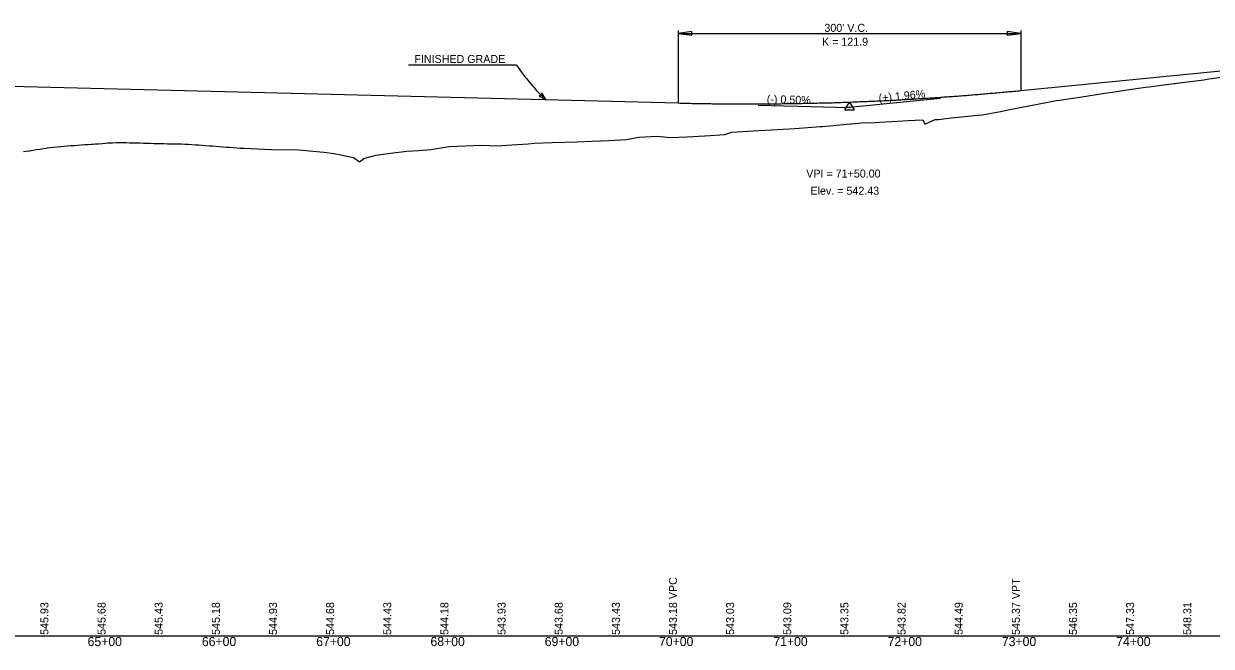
# Model space of a CAD drawing. Extents: x 49922 to 54713, y 49991 to 62800.
# Drawn here: x 52427 to 53466, y 61991 to 62535 of the extents above; entities that cross this region are included whole.
import ezdxf

# ---------------------------------------------------------------- set-up
doc = ezdxf.new("R2010")
doc.units = 0
for name, color, linetype in [('RD_DDB_GradeTX', 7, 'Continuous'), ('RD_DDB_Profile_EX', 7, 'Continuous'), ('RD_DDB_Profile_Lbl', 7, 'Continuous'), ('RD_DDB_Profile_PR', 7, 'Continuous'), ('RD_DDB_StaTX', 7, 'Continuous'), ('RD_DDB_StripGrade', 7, 'Continuous'), ('RD_DDB_VCLbl', 7, 'Continuous'), ('RD_GPK_Profile_Cell', 7, 'Continuous'), ('RD_TX_Profile', 7, 'Continuous')]:
    doc.layers.add(name, color=color, linetype=linetype)

msp = doc.modelspace()

# ---------------------------------------------------------------- linework, layer by layer
at = {"layer": 'RD_DDB_GradeTX'}
for p, q in [((53229.6, 62469.9), (53150, 62462.1)), ((53070, 62464.1), (53150, 62462.1)), ((53146, 62459.8), (53150, 62466.7)), ((53146, 62459.8), (53154, 62459.8)), ((53150, 62466.7), (53154, 62459.8))]:
    msp.add_line(p, q, dxfattribs=at)
msp.add_circle((53150, 62462.1), 0.529, dxfattribs=at)
at = {"layer": 'RD_DDB_Profile_EX'}
for points in [[(52783.7, 62425.3), (52799.8, 62427.8), (52827.9, 62429), (52841.5, 62428.3), (52854.6, 62429.3), (52868.8, 62430.3), (52874.3, 62430.7), (52889.8, 62431.5), (52911.6, 62431.9), (52924.9, 62432.5), (52939.4, 62433.2), (52954.9, 62434), (52965.6, 62436.1), (52981.7, 62437), (52993.4, 62435.7), (53007.7, 62436.4), (53023.2, 62437.2), (53023.6, 62437.2), (53041, 62438.5), (53046.9, 62440.3), (53070.3, 62441.9), (53081.8, 62442.3), (53102.2, 62443.7), (53124.5, 62445.3), (53126.2, 62445.4), (53150.7, 62447.6), (53151.9, 62447.7), (53160.5, 62448.5), (53172.5, 62448.9), (53176.2, 62449.2), (53192.2, 62449.9), (53201.3, 62450.5), (53207.4, 62450.9), (53214.1, 62451.3), (53215.8, 62447.4), (53216.4, 62447.8), (53225, 62451.4), (53227.7, 62451.6), (53238.9, 62453), (53256.3, 62454.7), (53259, 62455), (53265.9, 62455.6), (53282.2, 62458.6), (53290.3, 62460.2), (53306.8, 62463.3), (53331.2, 62468), (53333.6, 62468.4), (53353.2, 62471.4), (53358.8, 62472.2), (53373.3, 62474.5), (53383.9, 62476), (53393, 62477.4), (53409, 62479.6), (53412.3, 62480.1), (53422.7, 62481.6), (53434.1, 62482.9), (53434.9, 62483), (53436.5, 62483.2), (53459.9, 62486.3), (53464.5, 62486.9), (53484.9, 62489.6)], [(52427.3, 62423.4), (52429.4, 62423.8), (52432.4, 62424.2), (52435.4, 62424.7), (52438.5, 62425.2), (52441.5, 62425.6), (52444.5, 62426.1), (52447.5, 62426.5), (52448, 62426.6), (52450.6, 62426.9), (52453.6, 62427.3), (52456.6, 62427.6), (52459.6, 62428), (52460, 62428), (52462.7, 62428.2), (52465.7, 62428.4), (52468.7, 62428.6), (52471.7, 62428.8), (52474.7, 62429), (52477.8, 62429.3), (52480.8, 62429.5), (52483.8, 62429.6), (52486.8, 62429.8), (52488.3, 62429.9), (52489.9, 62430.1), (52492.9, 62430.3), (52495.9, 62430.6), (52498.9, 62430.8), (52500.7, 62431), (52502, 62431.1), (52505, 62431.2), (52508, 62431.4), (52509.8, 62431.5), (52511, 62431.4), (52514, 62431.3), (52517.1, 62431.3), (52520.1, 62431.2), (52523.1, 62431.1), (52526.1, 62431), (52529.2, 62431), (52532.2, 62430.9), (52535.2, 62430.8), (52538.2, 62430.7), (52541.2, 62430.6), (52544.3, 62430.5), (52547.3, 62430.4), (52550.3, 62430.4), (52553.3, 62430.3), (52556.4, 62430.2), (52559.4, 62430.2), (52560.6, 62430.3), (52561.3, 62430.3), (52562.4, 62430.2), (52565.6, 62430.1), (52568.5, 62430), (52570, 62429.9), (52571.5, 62429.8), (52574.5, 62429.6), (52577.5, 62429.4), (52580.5, 62429.2), (52583.6, 62429), (52586.6, 62428.7), (52589.6, 62428.5), (52592.6, 62428.3), (52595.7, 62428.1), (52598.7, 62427.9), (52601.7, 62427.6), (52604.7, 62427.4), (52607.8, 62427.2), (52610.8, 62427), (52613.8, 62426.8), (52616.8, 62426.5), (52620.2, 62426.3), (52631.9, 62425.7), (52644.2, 62425.1), (52668.1, 62425), (52690, 62422.8), (52699, 62421.6), (52716.1, 62418.2), (52720.9, 62414.8), (52721.3, 62414.4), (52724.9, 62417.3), (52735.4, 62420.4), (52748.2, 62421.9), (52762.7, 62423.8), (52772.7, 62424.5), (52783.7, 62425.3)]]:
    msp.add_lwpolyline(points, dxfattribs=at)
at = {"layer": 'RD_DDB_Profile_PR'}
for p, q in [((51800, 62495.9), (53000, 62465.9)), ((53300, 62476.8), (53500, 62496.4))]:
    msp.add_line(p, q, dxfattribs=at)
msp.add_spline([(53000, 62465.9), (53006, 62465.7), (53012, 62465.6), (53018, 62465.5), (53024, 62465.4), (53030, 62465.3), (53036, 62465.2), (53042, 62465.2), (53048, 62465.1), (53054, 62465.1), (53060, 62465.1), (53066, 62465.1), (53072, 62465.1), (53078, 62465.2), (53084, 62465.2), (53090, 62465.3), (53096, 62465.4), (53102, 62465.5), (53108, 62465.6), (53114, 62465.7), (53120, 62465.8), (53126, 62466), (53132, 62466.1), (53138, 62466.3), (53144, 62466.5), (53150, 62466.7), (53156, 62467), (53162, 62467.2), (53168, 62467.5), (53174, 62467.7), (53180, 62468), (53186, 62468.3), (53192, 62468.6), (53198, 62469), (53204, 62469.3), (53210, 62469.7), (53216, 62470), (53222, 62470.4), (53228, 62470.8), (53234, 62471.3), (53240, 62471.7), (53246, 62472.1), (53252, 62472.6), (53258, 62473.1), (53264, 62473.6), (53270, 62474.1), (53276, 62474.6), (53282, 62475.1), (53288, 62475.7), (53294, 62476.2), (53300, 62476.8)], degree=3, dxfattribs=at)
at = {"layer": 'RD_DDB_VCLbl'}
for p, q in [((53000, 62529.3), (53000, 62465.9)), ((53012, 62528.3), (53000, 62526.8)), ((53000, 62526.8), (53300, 62526.8)), ((53000, 62526.8), (53012, 62525.3)), ((53012, 62525.3), (53012, 62528.3)), ((53300, 62526.8), (53288, 62528.3)), ((53288, 62528.3), (53288, 62525.3)), ((53288, 62525.3), (53300, 62526.8)), ((53300, 62529.3), (53300, 62476.8))]:
    msp.add_line(p, q, dxfattribs=at)
at = {"layer": 'RD_GPK_Profile_Cell'}
msp.add_line((50000, 62000), (54700, 62000), dxfattribs=at)
at = {"layer": 'RD_TX_Profile'}
msp.add_line((52858.7, 62498.9), (52764.2, 62498.9), dxfattribs=at)
msp.add_lwpolyline([(52878.3, 62472), (52884.5, 62468.7), (52880.7, 62474.6)], close=True, dxfattribs=at)
msp.add_arc((53002, 62594.8), 172.4, 213.7803, 226.9981, dxfattribs=at)

# ---------------------------------------------------------------- texts
at = {"layer": 'RD_DDB_GradeTX'}
for s, rotation, p in [('(-) 0.50%', 358.5679, (53077.5, 62465.9)), ('(+) 1.96%', 5.5985, (53175.8, 62466.7))]:
    msp.add_text(s, height=7, rotation=rotation, dxfattribs=at).set_placement(p)
at = {"layer": 'RD_DDB_Profile_Lbl'}
for s, p in [('VPI = 71+50.00', (53112.1, 62400.7)), ('Elev. = 542.43', (53115.8, 62385.7))]:
    msp.add_text(s, height=7, dxfattribs=at).set_placement(p)
at = {"layer": 'RD_DDB_StaTX'}
for s, p in [('65+00', (52483.3, 61991)), ('66+00', (52583.3, 61991)), ('67+00', (52683.3, 61991)), ('68+00', (52783.3, 61991)), ('69+00', (52883.3, 61991)), ('70+00', (52983.3, 61991)), ('71+00', (53083.3, 61991)), ('72+00', (53183.3, 61991)), ('73+00', (53283.3, 61991)), ('74+00', (53383.3, 61991))]:
    msp.add_text(s, height=8, dxfattribs=at).set_placement(p)
at = {"layer": 'RD_DDB_StripGrade'}
for s, p in [('543.18 VPC', (52999, 62000.8)), ('545.37 VPT', (53299, 62000.8)), ('545.93', (52449, 62000.8)), ('545.68', (52499, 62000.8)), ('545.43', (52549, 62000.8)), ('545.18', (52599, 62000.8)), ('544.93', (52649, 62000.8)), ('544.68', (52699, 62000.8)), ('544.43', (52749, 62000.8)), ('544.18', (52799, 62000.8)), ('543.93', (52849, 62000.8)), ('543.68', (52899, 62000.8)), ('543.43', (52949, 62000.8)), ('543.18', (52999, 62000.8)), ('543.03', (53049, 62000.8)), ('543.09', (53099, 62000.8)), ('543.35', (53149, 62000.8)), ('543.82', (53199, 62000.8)), ('544.49', (53249, 62000.8)), ('545.37', (53299, 62000.8)), ('546.35', (53349, 62000.8)), ('547.33', (53399, 62000.8)), ('548.31', (53449, 62000.8))]:
    msp.add_text(s, height=7, rotation=90, dxfattribs=at).set_placement(p)
at = {"layer": 'RD_DDB_VCLbl'}
for s, p in [("300' V.C.", (53128, 62528.1)), ('K = 121.9', (53125.9, 62516))]:
    msp.add_text(s, height=7, dxfattribs=at).set_placement(p)
at = {"layer": 'RD_TX_Profile'}
msp.add_text('FINISHED GRADE', height=7, dxfattribs=at).set_placement((52769.2, 62500.9))

doc.saveas('drawing.dxf')
